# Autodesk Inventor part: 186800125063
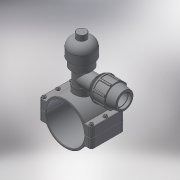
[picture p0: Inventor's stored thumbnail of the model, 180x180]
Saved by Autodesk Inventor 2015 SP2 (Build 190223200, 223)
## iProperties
Created: 2017-05
Part Number: 186800125063
Material: Generic
Description: PLASSON MECHANICAL TAPPING VALVE 125-63
Document SubType Name: Modeling
Designer: KIM
Density: 1 g/cm^3
Appearance: Default
Author: KIM
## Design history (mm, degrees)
derived "18680.ipt"
feature "Solid1::18680.ipt"
feature "Solid2::18680.ipt"
tag "TaggingFeature1"
body "Solid1"
other parameters: "d0" = 137.5, "d1" = 184, "d2" = 62.5, "d3" = 125, "d4" = 124, "d5" = 0, "d6" = 9.2, "d7" = 184, "d8" = 0.1, "d10" = 0, "d11" = 1.25, "d14" = 73.6528, "d20" = 1.25, "d23" = 1.25, "d36" = 13, "d37" = 10.4, "d38" = 70.5, "d39" = 0, "d40" = 3, "d41" = 5, "d42" = 0, "d43" = 8, "d44" = 3, "d45" = 0, "d46" = 1.25, "d51" = 94, "d52" = 56.656, "d53" = 21, "d54" = 0, "d57" = 0, "d58" = 135, "d60" = 0, "d62" = 13, "d63" = 10.4, "d66" = 103.2, "d67" = 63, "d68" = 16.66667, "d70" = 113, "d71" = 84.75, "d72" = 2.85714, "d73" = 90.4, "d74" = 120 deg, "d75" = 81.9, "d76" = 10 deg, "d77" = 101.7, "d80" = 50.4, "d82" = 11, "d87" = 28.57143, "d90" = 105.09, "d91" = 35 deg, "d92" = 17.5 deg, "d94" = 0, "d96" = 360 deg, "d98" = 1.26, "d99" = 121, "d100" = 67.8, "d101" = 135 deg, "d102" = 2.26, "d105" = 5.65, "d106" = 0, "d107" = 0.1, "d109" = 73.6528, "d112" = 34.85714, "d113" = 6.66667, "d116" = 0, "d121" = 67.9872, "d122" = 113.312, "d123" = 96.3152, "d124" = 45 deg, "d125" = 219.6, "d126" = 244, "d127" = 146.4, "d128" = 1, "d129" = 65, "d_" = 125, "G_" = 56.656, "A_" = 94, "L_" = 184, "L_1" = 124, "l_2" = 21, "d_1" = 63, "E_" = 113, "H_1" = 65, "H_2" = 244
